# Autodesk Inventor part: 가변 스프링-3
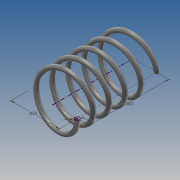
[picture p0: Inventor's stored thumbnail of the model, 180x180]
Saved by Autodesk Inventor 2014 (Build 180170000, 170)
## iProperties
Created: 2016-01
Part Number: 가변 스프링-3
Material: 스테인레스 스틸
Document SubType Name: Modeling
Designer: Administrator
Density: 8.08 g/cm^3
Appearance: 반연마
Mass: 8.67792 g
Surface Area: 21.7215 cm^2
Volume: 1.074 cm^3
Author: Administrator
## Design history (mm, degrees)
sketch "스케치1"
  geometry: L1 (0, 36.261)-(11, 36.261); L2 (11, 36.261)-(11, 0); L3 (11, 0)-(0, 0); L4 (0, 0)-(0, 36.261); C1 r 1 at (11, 0); 1 further point
  constraints: 8 end point, 2 coincident, 2 parallel, 1 centre point, 1 horizontal, 1 perpendicular
  dimensions: "d0" = 22 diameter of L2.end L4; "d1" = 36.2612 distance of L1.end L2.end (derived); "d2" = 2 diameter of C1
feature "코일1" pitch "d3" = 10; turns "d5" = 5; dims "d4" = 36.2612 (= d1), "d6" = 0, angle "d7" = 90 deg, angle "d8" = 90 deg, "d9" = 0, "d10" = 0
sketch "스케치2"
  geometry: L1 (-12, 0)-(-10, 0) reference; 1 further point
  constraints: 1 horizontal alignment
extrude "돌출1" cut sketch "스케치2" distance "d11" = 10; taper "d12" = 0 deg
node "작업 평면1"
sketch "스케치3"
  geometry: L1 (10, 0)-(12, 0) reference; 1 further point
  constraints: 1 horizontal alignment
extrude "돌출2" cut sketch "스케치3" distance "d14" = 10; taper "d15" = 0 deg
node "솔리드1"
node "절단 모서리 투영1"
node "절단 모서리 투영2"
other parameters: "d13" = 0
